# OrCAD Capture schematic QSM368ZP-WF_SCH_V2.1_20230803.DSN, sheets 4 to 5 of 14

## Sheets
4 PAGE04-LVDS&HDMIOUT: size A2
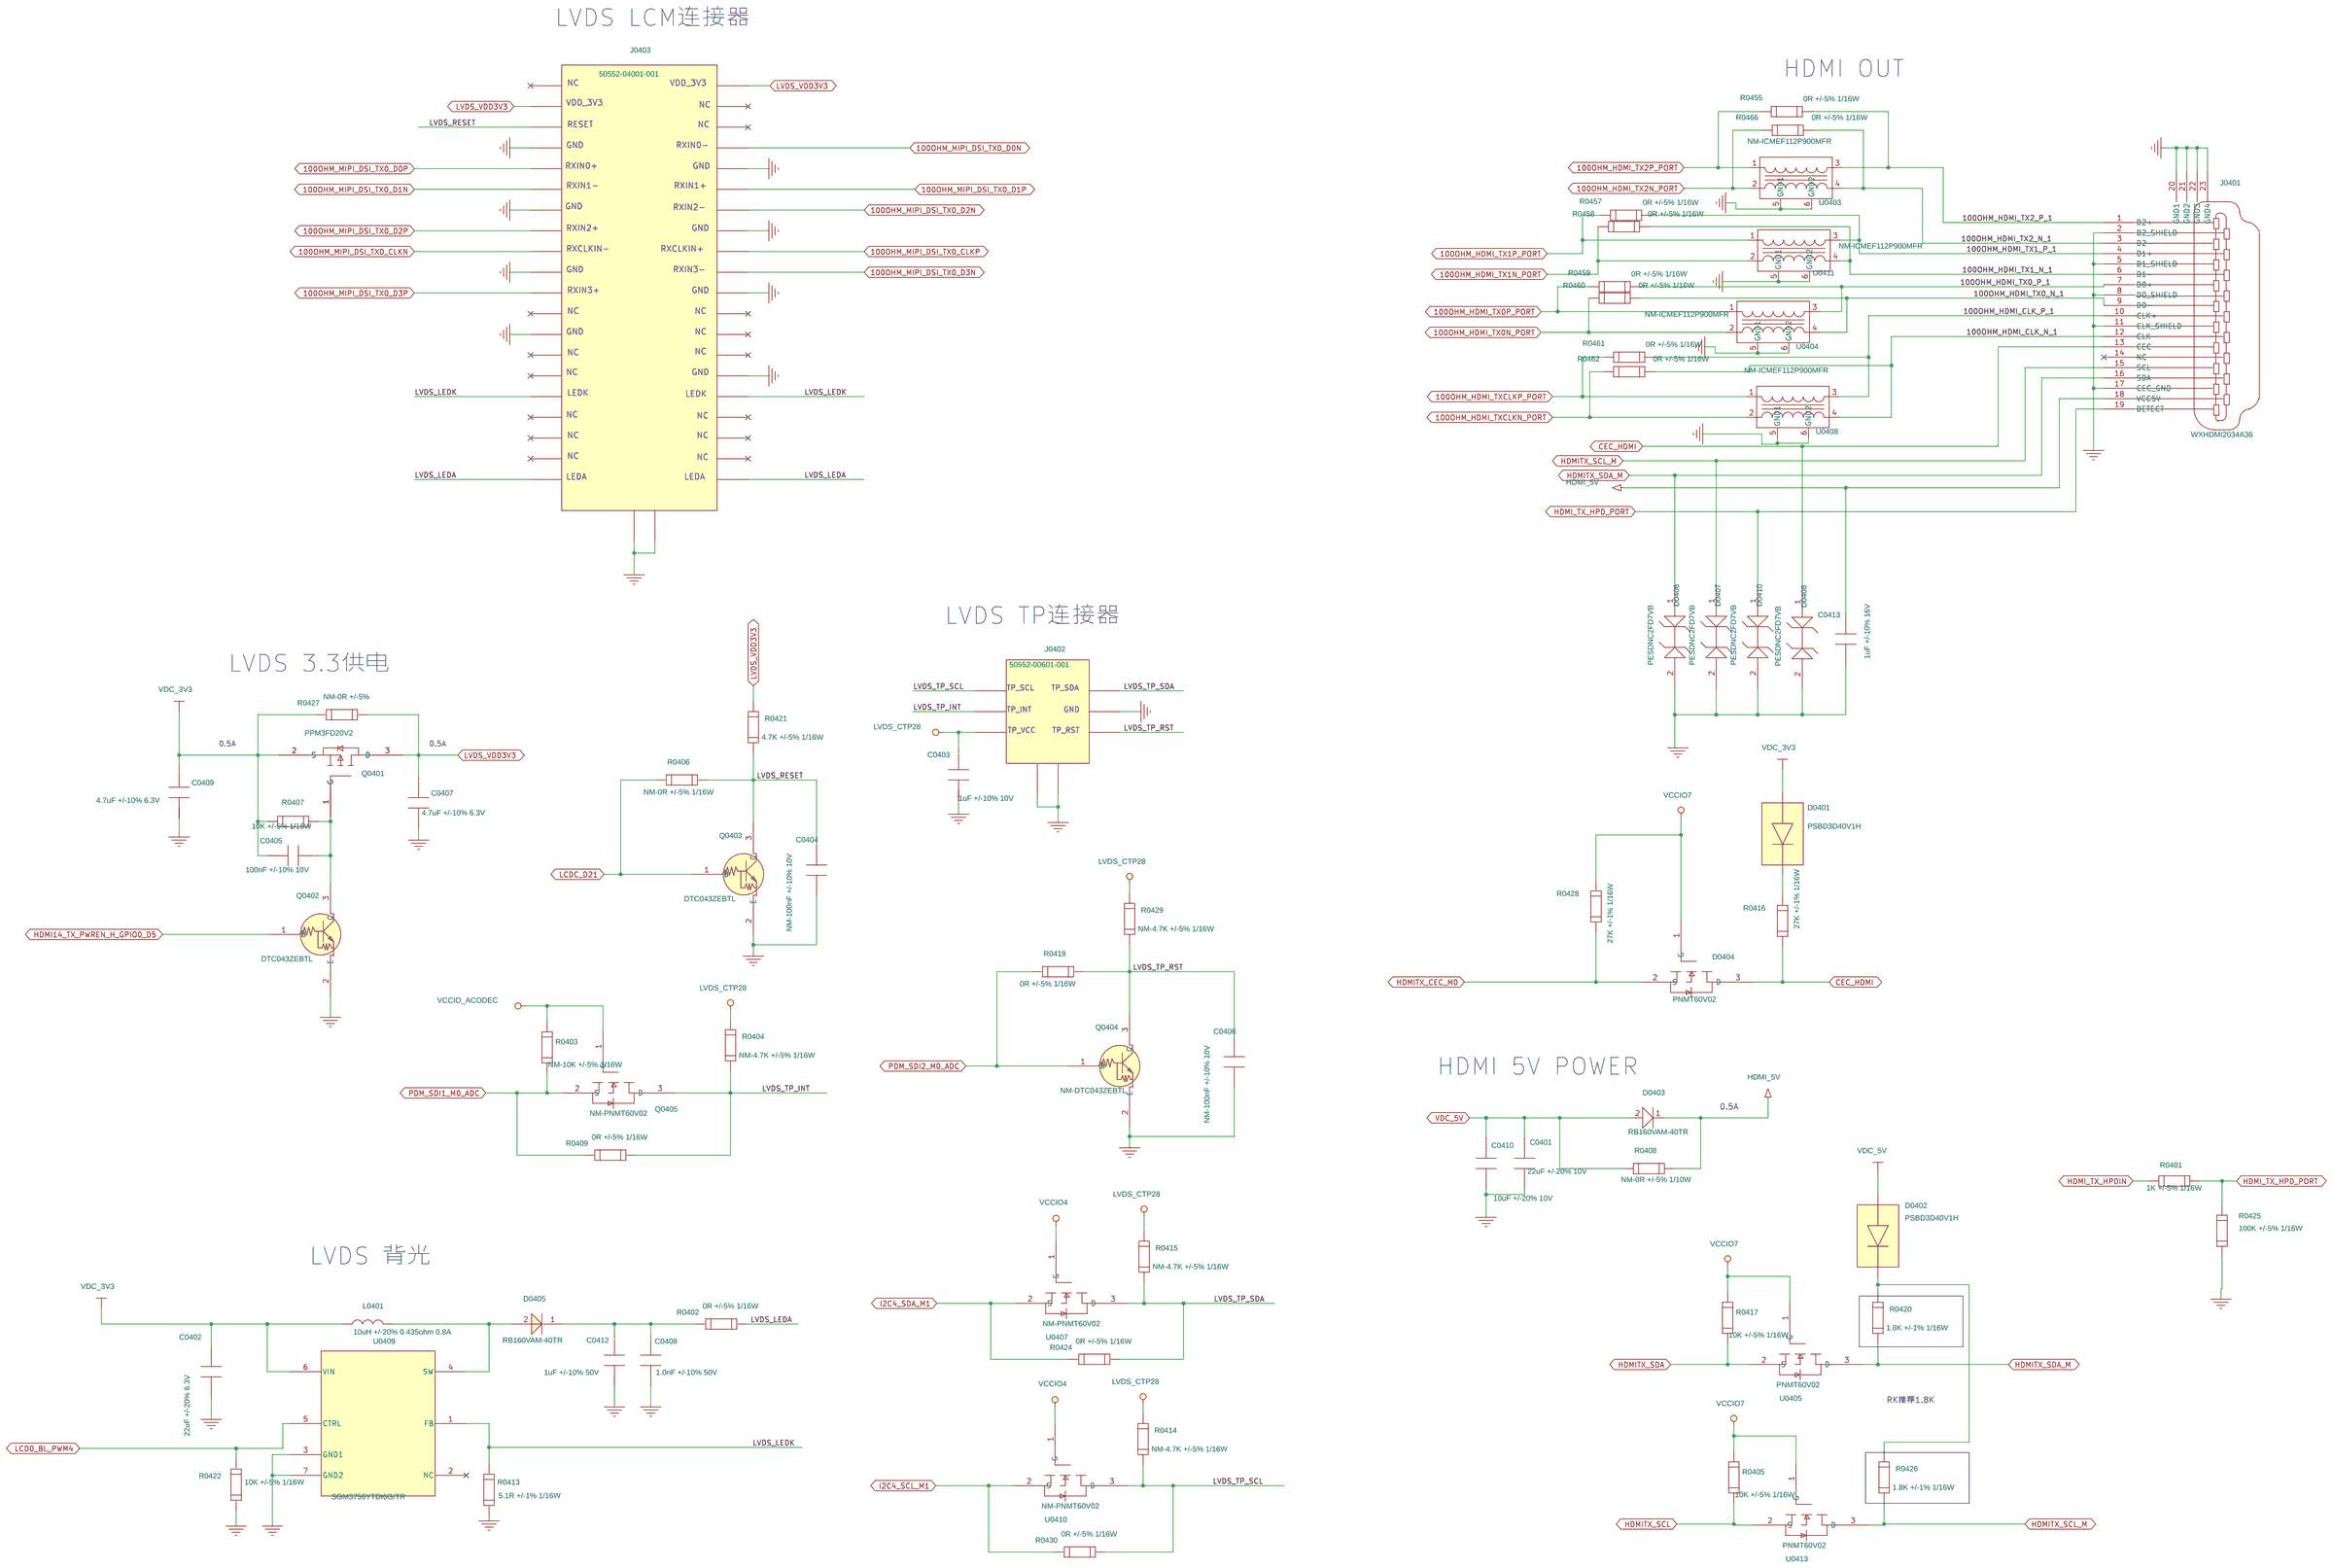
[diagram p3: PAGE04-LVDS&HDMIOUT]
5 PAGE05-MIPI&eDP: size A2
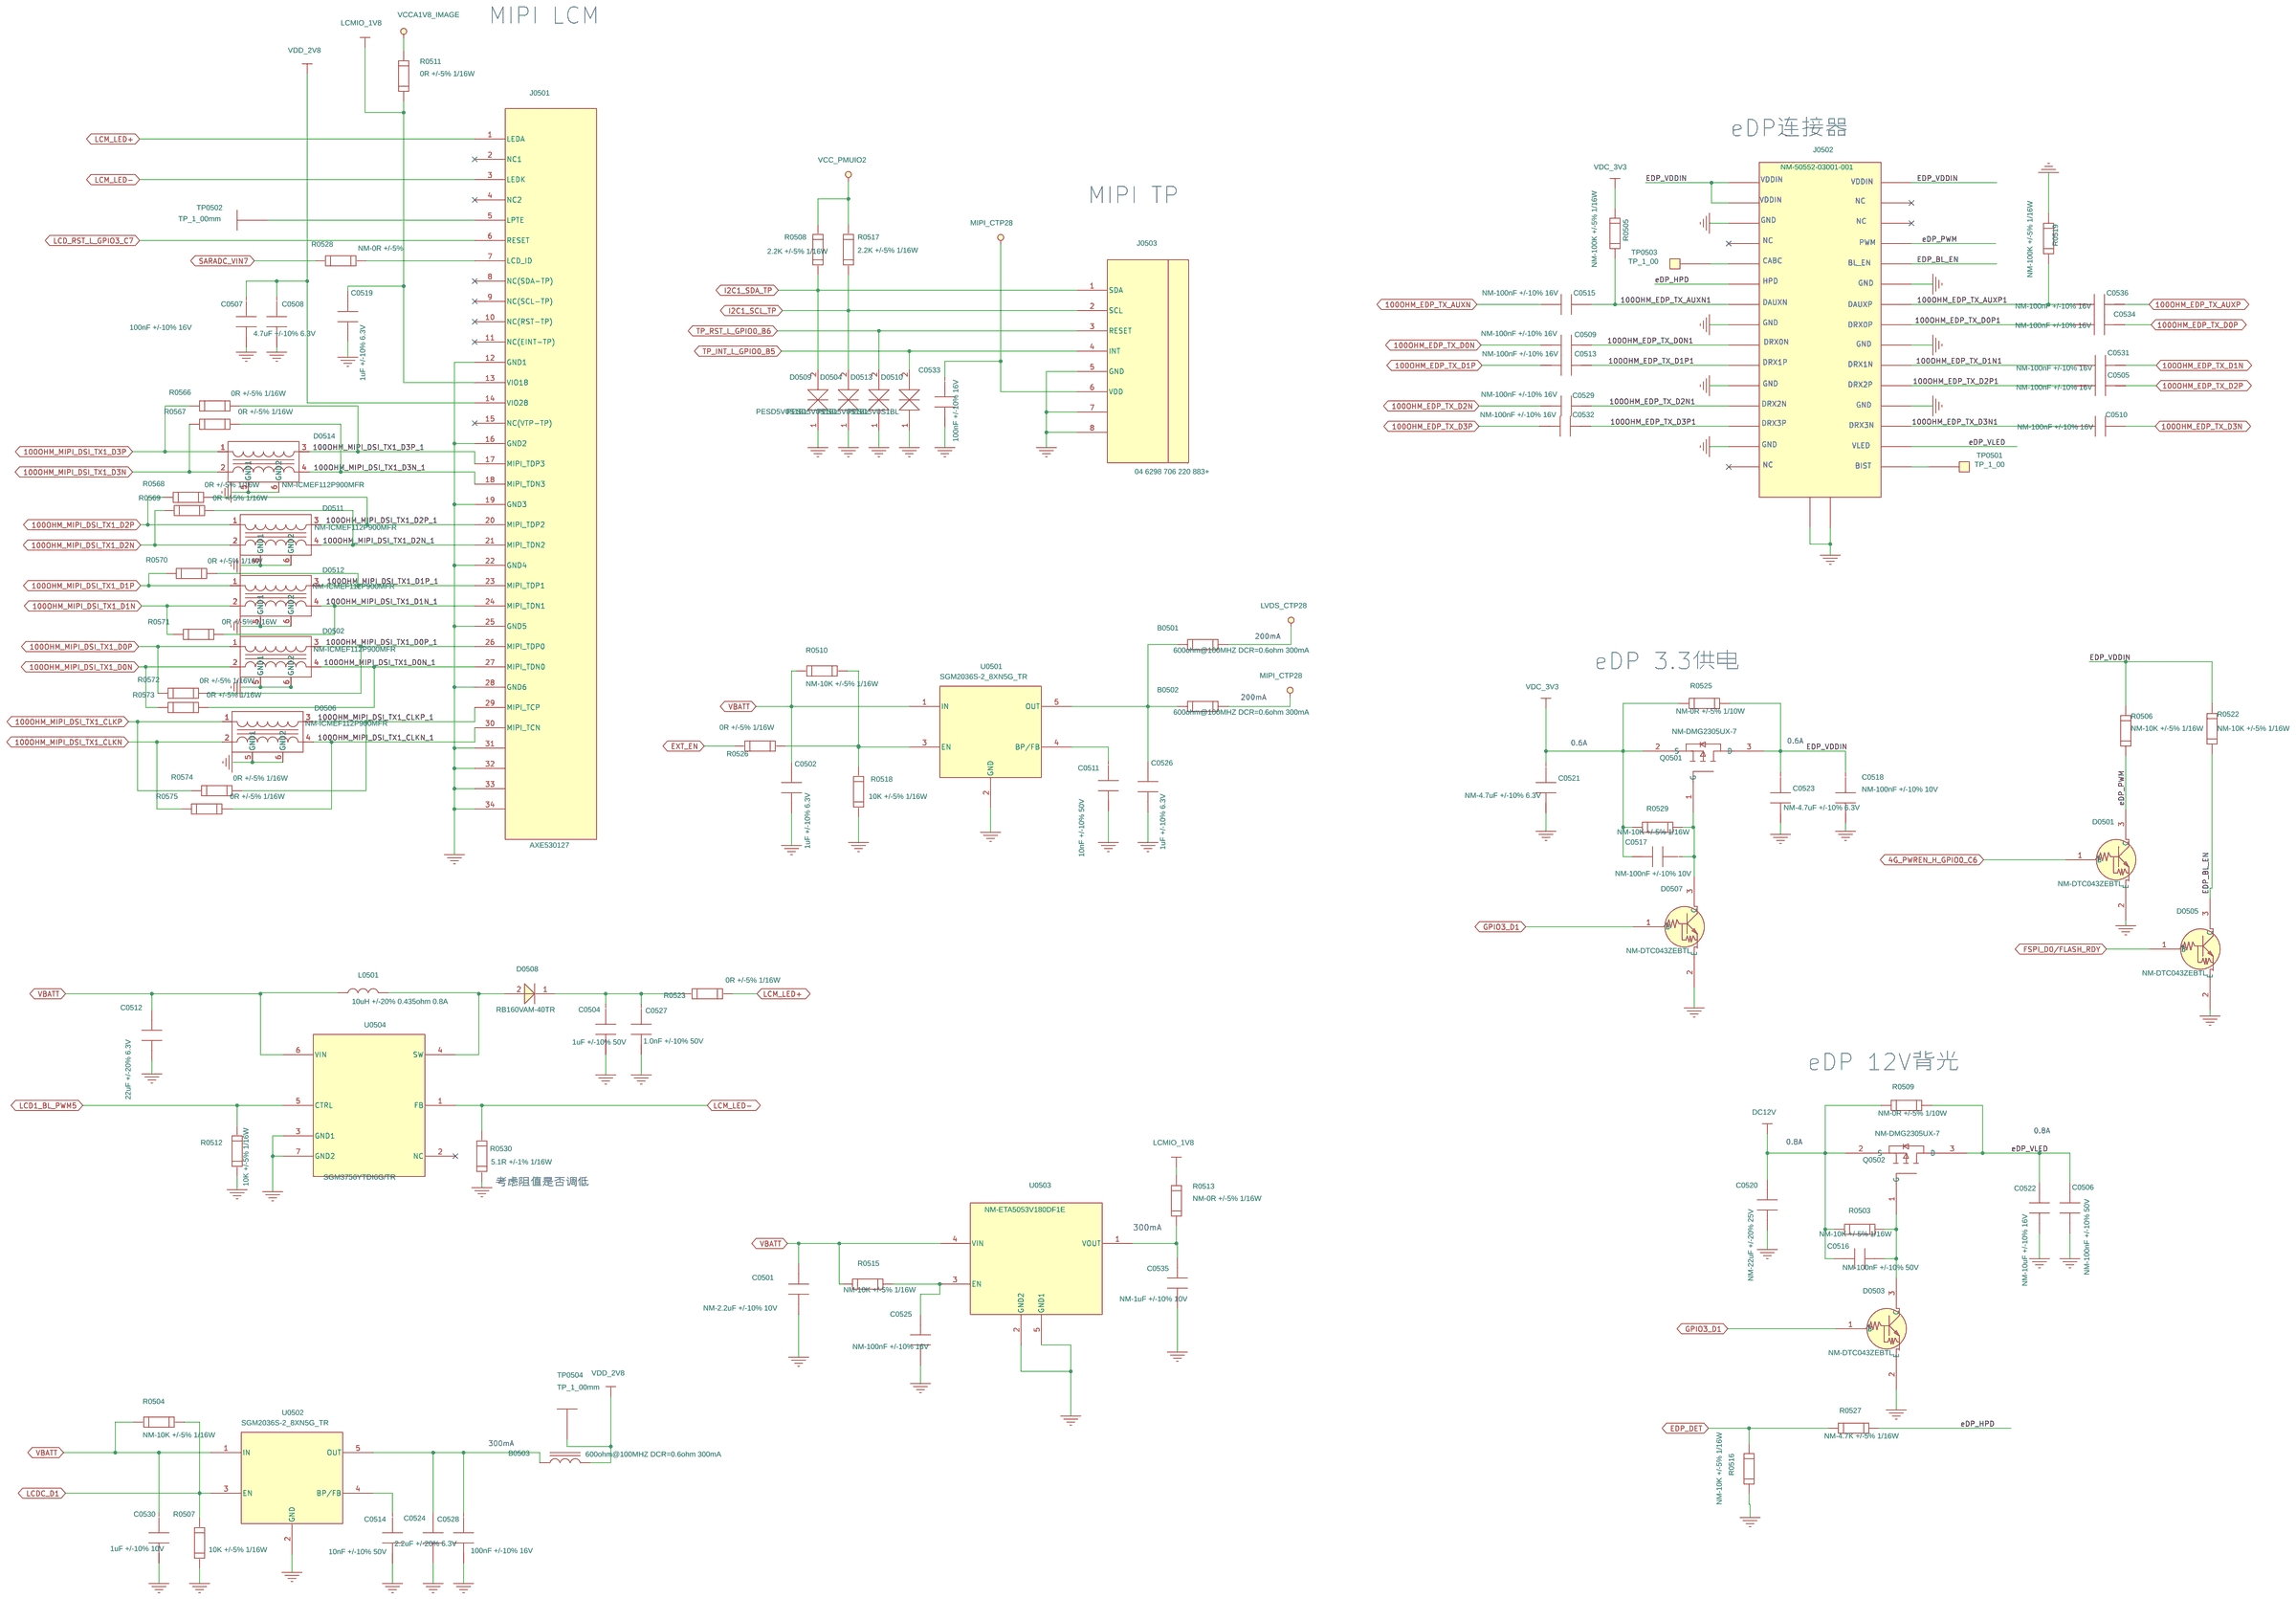
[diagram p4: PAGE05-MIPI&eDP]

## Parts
sheet PAGE04-LVDS&HDMIOUT
C0401  22uF +/-20% 10V  [c-0603_22_47uf_h1_00]
C0402  22uF +/-20% 6.3V  [c-0603_22_47uf_h1_00]
C0403  1uF +/-10% 10V  [C-0402]
C0404  NM-100nF +/-10% 10V  [C-0402]
C0405  100nF +/-10% 10V  [C-0402]
C0406  NM-100nF +/-10% 10V  [C-0402]
C0407  4.7uF +/-10% 6.3V  [C-0603]
C0408  1.0nF +/-10% 50V  [C-0402]
C0409  4.7uF +/-10% 6.3V  [C-0603]
C0410  10uF +/-20% 10V  [c-0603_22_47uf_h1_00]
C0412  1uF +/-10% 50V  [C-0805]
C0413  1uF +/-10% 16V  [C-0603]
D0401  PSBD3D40V1H  [PSBD3D40V1H]
D0402  PSBD3D40V1H  [PSBD3D40V1H]
D0403  RB160VAM-40TR  [RB160VA-40]
D0404  PNMT60V02  [PNMT60V02]
D0405  RB160VAM-40TR  [RB160VA-40]
D0406  PESDNC2FD7VB  [PESDNC2FD7VB]
D0407  PESDNC2FD7VB  [PESDNC2FD7VB]
D0408  PESDNC2FD7VB  [PESDNC2FD7VB]
D0410  PESDNC2FD7VB  [PESDNC2FD7VB]
J0401  WXHDMI2034A36  [WXHDMI2034A36]
J0402  50552-00601-001  [50552-00601-001_PINS8_7D5x3D4]
J0403  50552-04001-001  [50552-04001-001_PINS42_24D5x3D4]
L0401  10uH +/-20% 0.435ohm 0.8A  [L-2520]
Q0401  PPM3FD20V2  [WPM3027]
Q0402  DTC043ZEBTL  [DTC043ZEBTL]
Q0403  DTC043ZEBTL  [DTC043ZEBTL]
Q0404  NM-DTC043ZEBTL  [DTC043ZEBTL]
Q0405  NM-PNMT60V02  [PNMT60V02]
R0401  1K +/-5% 1/16W  [R-0402]
R0402  0R +/-5% 1/16W  [R-0402]
R0403  NM-10K +/-5% 1/16W  [R-0402]
R0404  NM-4.7K +/-5% 1/16W  [R-0402]
R0405  10K +/-5% 1/16W  [R-0402]
R0406  NM-0R +/-5% 1/16W  [R-0402]
R0407  10K +/-5% 1/16W  [R-0402]
R0408  NM-0R +/-5% 1/10W  [R-0603]
R0409  0R +/-5% 1/16W  [R-0402]
R0413  5.1R +/-1% 1/16W  [R-0402]
R0414  NM-4.7K +/-5% 1/16W  [R-0402]
R0415  NM-4.7K +/-5% 1/16W  [R-0402]
R0416  27K +/-1% 1/16W  [R-0402]
R0417  10K +/-5% 1/16W  [R-0402]
R0418  0R +/-5% 1/16W  [R-0402]
R0420  1.8K +/-1% 1/16W  [R-0402]
R0421  4.7K +/-5% 1/16W  [R-0402]
R0422  10K +/-5% 1/16W  [R-0402]
R0424  0R +/-5% 1/16W  [R-0402]
R0425  100K +/-5% 1/16W  [R-0402]
R0426  1.8K +/-1% 1/16W  [R-0402]
R0427  NM-0R +/-5%  [R-0402]
R0428  27K +/-1% 1/16W  [R-0402]
R0429  NM-4.7K +/-5% 1/16W  [R-0402]
R0430  0R +/-5% 1/16W  [R-0402]
R0455  0R +/-5% 1/16W  [R-0402]
R0457  0R +/-5% 1/16W  [R-0402]
R0458  0R +/-5% 1/16W  [R-0402]
R0459  0R +/-5% 1/16W  [R-0402]
R0460  0R +/-5% 1/16W  [R-0402]
R0461  0R +/-5% 1/16W  [R-0402]
R0462  0R +/-5% 1/16W  [R-0402]
R0466  0R +/-5% 1/16W  [R-0402]
U0403  NM-ICMEF112P900MFR  [ICMEF112P900MFR]
U0404  NM-ICMEF112P900MFR  [ICMEF112P900MFR]
U0405  PNMT60V02  [PNMT60V02]
U0407  NM-PNMT60V02  [PNMT60V02]
U0408  NM-ICMEF112P900MFR  [ICMEF112P900MFR]
U0409  SGM3756YTDI6G/TR  [SGM3756YTDI6G_TR_PINS7_2x2]
U0410  NM-PNMT60V02  [PNMT60V02]
U0411  NM-ICMEF112P900MFR  [ICMEF112P900MFR]
U0413  PNMT60V02  [PNMT60V02]
sheet PAGE05-MIPI&eDP
B0501  600ohm@100MHZ DCR=0.6ohm 300mA  [R-0402]
B0502  600ohm@100MHZ DCR=0.6ohm 300mA  [R-0402]
B0503  600ohm@100MHZ DCR=0.6ohm 300mA  [B-0402]
C0501  NM-2.2uF +/-10% 10V  [C-0402]
C0502  1uF +/-10% 6.3V  [C-0402]
C0504  1uF +/-10% 50V  [C-0805]
C0505  NM-100nF +/-10% 16V  [C-0402]
C0506  NM-100nF +/-10% 50V  [C-0603]
C0507  100nF +/-10% 16V  [C-0402]
C0508  4.7uF +/-10% 6.3V  [C-0603]
C0509  NM-100nF +/-10% 16V  [C-0402]
C0510  NM-100nF +/-10% 16V  [C-0402]
C0511  10nF +/-10% 50V  [C-0402]
C0512  22uF +/-20% 6.3V  [c-0603_22_47uf_h1_00]
C0513  NM-100nF +/-10% 16V  [C-0402]
C0514  10nF +/-10% 50V  [C-0402]
C0515  NM-100nF +/-10% 16V  [C-0402]
C0516  NM-100nF +/-10% 50V  [C-0603]
C0517  NM-100nF +/-10% 10V  [C-0402]
C0518  NM-100nF +/-10% 10V  [C-0402]
C0519  1uF +/-10% 6.3V  [C-0402]
C0520  NM-22uF +/-20% 25V  [C-0805_H1_45]
C0521  NM-4.7uF +/-10% 6.3V  [C-0603]
C0522  NM-10uF +/-10% 16V  [C-0805_H1_45]
C0523  NM-4.7uF +/-10% 6.3V  [C-0603]
C0524  2.2uF +/-20% 6.3V  [C-0402]
C0525  NM-100nF +/-10% 16V  [C-0402]
C0526  1uF +/-10% 6.3V  [C-0402]
C0527  1.0nF +/-10% 50V  [C-0402]
C0528  100nF +/-10% 16V  [C-0402]
C0529  NM-100nF +/-10% 16V  [C-0402]
C0530  1uF +/-10% 10V  [C-0402]
C0531  NM-100nF +/-10% 16V  [C-0402]
C0532  NM-100nF +/-10% 16V  [C-0402]
C0533  100nF +/-10% 16V  [C-0402]
C0534  NM-100nF +/-10% 16V  [C-0402]
C0535  NM-1uF +/-10% 10V  [C-0402]
C0536  NM-100nF +/-10% 16V  [C-0402]
D0501  NM-DTC043ZEBTL  [DTC043ZEBTL]
D0502  NM-ICMEF112P900MFR  [ICMEF112P900MFR]
D0503  NM-DTC043ZEBTL  [DTC043ZEBTL]
D0504  PESD5V0S1BL  [PESD5V0S1BL]
D0505  NM-DTC043ZEBTL  [DTC043ZEBTL]
D0506  NM-ICMEF112P900MFR  [ICMEF112P900MFR]
D0507  NM-DTC043ZEBTL  [DTC043ZEBTL]
D0508  RB160VAM-40TR  [RB160VA-40]
D0509  PESD5V0S1BL  [PESD5V0S1BL]
D0510  PESD5V0S1BL  [PESD5V0S1BL]
D0511  NM-ICMEF112P900MFR  [ICMEF112P900MFR]
D0512  NM-ICMEF112P900MFR  [ICMEF112P900MFR]
D0513  PESD5V0S1BL  [PESD5V0S1BL]
D0514  NM-ICMEF112P900MFR  [ICMEF112P900MFR]
J0501  AXE530127  [AXE530127]
J0502  NM-50552-03001-001  [50552-03001-001_PINS32_19D5x3D4]
J0503  04 6298 706 220 883+  [6298706220883]
L0501  10uH +/-20% 0.435ohm 0.8A  [L-2520]
Q0501  NM-DMG2305UX-7  [DMG2305UX-7]
Q0502  NM-DMG2305UX-7  [DMG2305UX-7]
R0503  NM-10K +/-5% 1/16W  [R-0402]
R0504  NM-10K +/-5% 1/16W  [R-0402]
R0505  NM-100K +/-5% 1/16W  [R-0402]
R0506  NM-10K +/-5% 1/16W  [R-0402]
R0507  10K +/-5% 1/16W  [R-0402]
R0508  2.2K +/-5% 1/16W  [R-0402]
R0509  NM-0R +/-5% 1/10W  [R-0603]
R0510  NM-10K +/-5% 1/16W  [R-0402]
R0511  0R +/-5% 1/16W  [R-0402]
R0512  10K +/-5% 1/16W  [R-0402]
R0513  NM-0R +/-5% 1/16W  [R-0402]
R0515  NM-10K +/-5% 1/16W  [R-0402]
R0516  NM-10K +/-5% 1/16W  [R-0402]
R0517  2.2K +/-5% 1/16W  [R-0402]
R0518  10K +/-5% 1/16W  [R-0402]
R0519  NM-100K +/-5% 1/16W  [R-0402]
R0522  NM-10K +/-5% 1/16W  [R-0402]
R0523  0R +/-5% 1/16W  [R-0402]
R0525  NM-0R +/-5% 1/10W  [R-0603]
R0526  0R +/-5% 1/16W  [R-0402]
R0527  NM-4.7K +/-5% 1/16W  [R-0402]
R0528  NM-0R +/-5%  [R-0402]
R0529  NM-10K +/-5% 1/16W  [R-0402]
R0530  5.1R +/-1% 1/16W  [R-0402]
R0566  0R +/-5% 1/16W  [R-0402]
R0567  0R +/-5% 1/16W  [R-0402]
R0568  0R +/-5% 1/16W  [R-0402]
R0569  0R +/-5% 1/16W  [R-0402]
R0570  0R +/-5% 1/16W  [R-0402]
R0571  0R +/-5% 1/16W  [R-0402]
R0572  0R +/-5% 1/16W  [R-0402]
R0573  0R +/-5% 1/16W  [R-0402]
R0574  0R +/-5% 1/16W  [R-0402]
R0575  0R +/-5% 1/16W  [R-0402]
TP0501  TP_1_00  [TP_1_00]
TP0502  TP_1_00mm  [TP_1_00]
TP0503  TP_1_00  [TP_1_00]
TP0504  TP_1_00mm  [TP_1_00]
U0501  SGM2036S-2_8XN5G_TR  [SGM2036S-2_8XN5G_TR_PINS5_2D92X1D6]
U0502  SGM2036S-2_8XN5G_TR  [SGM2036S-2_8XN5G_TR_PINS5_2D92X1D6]
U0503  NM-ETA5053V180DF1E  [ETA5053V180DF1E]
U0504  SGM3756YTDI6G/TR  [SGM3756YTDI6G_TR_PINS7_2x2]

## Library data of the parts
C0401 = c-0603_22_47uf_H1_00: Application_Level: 通用; DataRecord: 2017-08-09; Geometry Height: 1.0mm; Lib_Name: 电容; MPN: CC0603MRX5R6BB226; Manufacturer: YAGEO; Part Description: CAP X5R 22uF +/-20% 10V CH0603 1.6x0.8mm H1mm RO; Part Number: QT0012102005; Rev.Date: 2022-09-21
C0402 C0512 = c-0603_22_47uf_H1_00: Application_Level: 通用; DataRecord: 2017-08-09; Geometry Height: 1MM; Lib_Name: 电容; MPN: CC0603MRX5R5BB226; Manufacturer: YAGEO; Part Description: CAP X5R 22uF +/-20% 6.3V CH0603 1.6x0.8mm H1mm RO; Part Number: QT0012000626; Rev.Date: 2022-09-21
C0403 C0530 = C-0402_v2: DataRecord: 2017-08-09; Geometry Height: 0.5mm; MPN: CC0402KRX5R6BB105; Manufacturer: YAGEO; Part Description: CAP X5R 1uF +/-10% 10V CH0402 H0.55mm RO; Part Number: QT0012000349; Rev.Date: 2022-08-17; SCH Part: C
C0404 C0406 = C: Application_Level: Common(通用); BOMRemark: NM; DataRecord: 2017-08-09; Geometry Height: 0.5mm; Lib_Name: 电容; MPN: CC0402KRX7R6BB104; Manufacturer: YAGEO; Part Description: CAP X7R 100nF +/-10% 10V CH0402 H0.55mm RO; Part Number: QT0012000328; Rev.Date: 2021-12-15
C0405 = C-0402_v2: DataRecord: 2017-08-09; Geometry Height: 0.5mm; MPN: CC0402KRX7R6BB104; Manufacturer: YAGEO; Part Description: CAP X7R 100nF +/-10% 10V CH0402 H0.55mm RO; Part Number: QT0012000328; Rev.Date: 2022-08-17; SCH Part: C
C0407 C0409 C0508 = C-0603: DataRecord: 2017-08-09; Geometry Height: 0.8mm; Geometry.Height: 0.5mm; MPN: CC0603KRX5R5BB475; Manufacturer: YAGEO; Part Description: CAP X5R 4.7uF +/-10% 6.3V CH0603 H0.9mm RO; Part Number: QT0012100596; Rev.Date: 2022-08-17; SCH Part: C
C0408 C0527 = C-0402_v2: DataRecord: 2017-08-09; Geometry Height: 0.5mm; MPN: CC0402KRX7R9BB102; Manufacturer: YAGEO; Part Description: CAP X7R 1.0nF +/-10% 50V CH0402 H0.55mm RO; Part Number: QT0012100276; Rev.Date: 2022-08-17; SCH Part: C
C0410 = c-0603_22_47uf_H1_00: Application_Level: 通用; DataRecord: 2017-08-09; Geometry Height: 1MM; Lib_Name: 电容; MPN: CC0603MRX5R6BB106; Manufacturer: YAGEO; Part Description: CAP X5R 10uF +/-20% 10V CH0603 1.6x0.8mm H1mm RO; Part Number: QT0012001350; Rev.Date: 2022-09-21
C0412 C0504 = C-0805_v2: DataRecord: 2017-08-09; Geometry Height: 1.45MM; MPN: CC0805KKX7R9BB105; Manufacturer: YAGEO; Part Description: CAP X7R 1uF +/-10% 50V CH0805 H1.45mm RO; Part Number: QT0012002024; Rev.Date: 2022-08-17; SCH Part: C-0805_H1_45
C0413 = C: Application_Level: Limited(限制); DataRecord: 2017-08-09; Geometry Height: 0.8mm; Lib_Name: 电容; MPN: CC0603KRX5R7BB105; Manufacturer: YAGEO; Part Description: CAP X5R 1uF +/-10% 16V CH0603 H0.9mm RO; Part Number: QT0012000033; Rev.Date: 2022-08-17
D0401 D0402 = PSBD3D40V1H: Application_Level: Common(通用); DataRecord: 2020-02-20; Geometry Height: 1.0mm; Lib_Name: 二极管; Manufacturer: PRISEMI; Part Description: DIO Schottky Vr=40V IF=1A SOD-323 RO; Part Number: QT0015101060; Rev.Date: 2022-09-20
D0403 = RB160VA-40_v2: Application_Level: Common(通用); DataRecord: 2018-06-26; Geometry Height: 0.5mm; Lib_Name: 二极管; Manufacturer: ROHM; Part Description: DIO Schottky Vr=40V IF=1A TUMD2M RO; Part Number: QT0015101042; Rev.Date: 2022-08-17
D0404 U0405 U0413 = PNMT60V02: Application_Level: Common(通用); DataRecord: 2020-05-25; Geometry Height: 1.11mm; Lib_Name: MOS管; Manufacturer: PRISEMI; Part Description: AUD NMOS VDS=60V 0.18A Vth=0.5~1.5V SOT-23 RO; Part Number: QT0015401037; Rev.Date: 2022-09-20
D0405 D0508 = RB160VA-40: DataRecord: 2018-06-26; Geometry Height: 0.5mm; Manufacturer: ROHM; Part Description: DIO Schottky Vr=40V IF=1A TUMD2M RO; Part Number: QT0015101042; Rev.Date: 2022-08-17
D0406 D0407 D0408 D0410 = PESDNC2FD7VB: Application_Level: Common(通用); DataRecord: 2020-03-06; Geometry Height: 0.5mm; Lib_Name: ESD&EMI&TVS; Manufacturer: PRISEMI; Part Description: TVS Bi Vrwm=7V 21pF DFN1006-2L RO; Part Number: QT0013501082; Rev.Date: 2022-09-20
J0401 = WXHDMI2034A36: Application_Level: 限制（Others）; DataRecord: 2017-08-09; Geometry Height: 6.1mm; Lib_Name: 结构连接器; Manufacturer: XINGWANG; Part Description: CON TYPE-A HDMI FEMALE 19PIN 0.5PITCH 15x14mm H6.1mm RO; Part Number: QT0016601009; Rev.Date: 2022-08-17
J0402 = 50552-00601-001: Application_Level: 限制（Others）; DataRecord: 2023-02-22; Geometry Height: 4.35mm; Lib_Name: 结构连接器; Manufacturer: ACES; Part Description: CON BTB FEMALE 2x3Pin 1.0pitch SMT PINS8 7.5x3.4mm H4.35mm RO; Part Number: QT0016201827; Rev.Date: 2023-02-22
J0403 = 50552-04001-001: Application_Level: 限制（Others）; DataRecord: 2023-02-22; Geometry Height: 4.35mm; Lib_Name: 结构连接器; Manufacturer: ACES; Part Description: CON BTB FEMALE 2x20Pin 1.0pitch SMT PINS42 24.5x3.4mm H4.35mm RO; Part Number: QT0016201829; Rev.Date: 2023-02-22
L0401 L0501 = L: Application_Level: 通用; DataRecord: 2017-09-05; Geometry Height: 1.0mm; Lib_Name: 电感&磁珠; MPN: WPN252010HS100MT; Manufacturer: SUNLORD; Part Description: IND LOW 10uH +/-20% 0.435ohm 0.8A 2.5x2.0mm H1.0mm RO; Part Number: QT0014103254; Rev.Date: 2022-08-17
Q0401 = WPM3027: Application_Level: Common(通用); DataRecord: 2022-10-14; Geometry Height: 0.498mm; Lib_Name: MOS管; Manufacturer: PRISEMI; Part Description: AUD PMOS VDS=-20V -2A Vth=-0.45~-0.85V R19 DFN1006-3L PINS3 0.98x0.58mm H0.498mm RO; Part Number: QT0015401117; Rev.Date: 2022-10-14
Q0402 Q0403 = DTC043ZEBTL: Application_Level: Common(通用); DataRecord: 2017-08-09; Geometry Height: 0.6mm; Lib_Name: 三极管; Manufacturer: ROHM; Part Description: AUD Digital NPN 50V 100mA R1=4.7K R2=47K EMT3F RO; Part Number: QT0015200080; Rev.Date: 2022-08-17
D0501 D0503 D0505 D0507 Q0404 = DTC043ZEBTL: Application_Level: Common(通用); BOMRemark: NM; DataRecord: 2017-08-09; Geometry Height: 0.6mm; Lib_Name: 三极管; Manufacturer: ROHM; Part Description: AUD Digital NPN 50V 100mA R1=4.7K R2=47K EMT3F RO; Part Number: QT0015200080; Rev.Date: 2021-12-15
Q0405 U0407 U0410 = PNMT60V02: Application_Level: Common(通用); BOMRemark: NM; DataRecord: 2020-05-25; Geometry Height: 1.11mm; Lib_Name: MOS管; Manufacturer: PRISEMI; Part Description: AUD NMOS VDS=60V 0.18A Vth=0.5~1.5V SOT-23 RO; Part Number: QT0015401037; Rev.Date: 2021-10-25
R0401 = R-0402: Application_Level: 通用; DataRecord: 2017-08-09; Geometry Height: 0.4MM; Lib_Name: 电阻; MPN: RC0402JR-071KL; Manufacturer: YAGEO; Part Description: RES MF 1K +/-5% 1/16W CH0402 H0.4mm RO; Part Number: QT0011000489; Rev.Date: 2022-08-17
R0402 R0409 R0424 R0430 R0523 R0526 = R-0402_v3: DataRecord: 2017-08-09; Geometry Height: 0.4MM; MPN: RC0402JR-070RL; Manufacturer: YAGEO; Part Description: RES MF 0R +/-5% 1/16W CH0402 H0.4mm RO; Part Number: QT0011000094; Rev.Date: 2022-08-17
R0403 = R-0402: Application_Level: 通用; BOMRemark: NM; DataRecord: 2017-08-09; Geometry Height: 0.4MM; Lib_Name: 电阻; MPN: RC0402JR-0710KL; Manufacturer: YAGEO; Part Description: RES MF 10K +/-5% 1/16W CH0402 H0.4mm RO; Part Number: QT0011000453; Rev.Date: 2022-08-17
R0404 R0414 R0415 R0429 = R-0402: Application_Level: Common(通用); BOMRemark: NM; DataRecord: 2017-08-09; Geometry Height: 0.4MM; Lib_Name: 电阻; MPN: RC0402JR-074K7L; Manufacturer: YAGEO; Part Description: RES MF 4.7K +/-5% 1/16W CH0402 H0.4mm RO; Part Number: QT0011000456; Rev.Date: 2021-12-15
R0405 R0417 = R-0402: Application_Level: 通用; DataRecord: 2017-08-09; Geometry Height: 0.4MM; Lib_Name: 电阻; MPN: RC0402JR-0710KL; Manufacturer: YAGEO; Part Description: RES MF 10K +/-5% 1/16W CH0402 H0.4mm RO; Part Number: QT0011000453; Rev.Date: 2022-08-17
R0406 = R-0402_v3: Application_Level: Common(通用); BOMRemark: NM; DataRecord: 2017-08-09; Geometry Height: 0.4MM; Lib_Name: 电阻; MPN: RC0402JR-070RL; Manufacturer: YAGEO; Part Description: RES MF 0R +/-5% 1/16W CH0402 H0.4mm RO; Part Number: QT0011000094; Rev.Date: 2021-12-15
R0407 = R-0402: Application_Level: Common(通用); DataRecord: 2017-08-09; Geometry Height: 0.4MM; Lib_Name: 电阻; MPN: RC0402JR-0710KL; Manufacturer: YAGEO; Part Description: RES MF 10K +/-5% 1/16W CH0402 H0.4mm RO; Part Number: QT0011000453; Rev.Date: 2022-08-17
R0408 R0509 R0525 = R-0603: Application_Level: 通用; BOMRemark: NM; DataRecord: 2017-08-09; Geometry Height: 0.55MM; Lib_Name: 电阻; MPN: RC0603JR-070RL; Manufacturer: YAGEO; Part Description: RES MF 0R +/-5% 1/10W CH0603 H0.55mm RO; Part Number: QT0011000610; Rev.Date: 2022-08-17
R0413 R0530 = R-0402_v3: Application_Level: 通用; DataRecord: 2017-08-09; Geometry Height: 0.4MM; Lib_Name: 电阻; MPN: RC0402FR-075R1L; Manufacturer: YAGEO; Part Description: RES MF 5.1R +/-1% 1/16W CH0402 H0.4mm RO; Part Number: QT0011003032; Rev.Date: 2022-08-17
R0416 R0428 = R-0402: Application_Level: 通用; DataRecord: 2017-08-09; Geometry Height: 0.4MM; Lib_Name: 电阻; MPN: RC0402FR-0727KL; Manufacturer: YAGEO; Part Description: RES MF 27K +/-1% 1/16W CH0402 H0.4mm RO; Part Number: QT0011003062; Rev.Date: 2022-08-17
R0418 = R-0402_v3: Application_Level: Common(通用); DataRecord: 2017-08-09; Geometry Height: 0.4MM; Lib_Name: 电阻; MPN: RC0402JR-070RL; Manufacturer: YAGEO; Part Description: RES MF 0R +/-5% 1/16W CH0402 H0.4mm RO; Part Number: QT0011000094; Rev.Date: 2022-08-17
R0420 R0426 = R-0402: Application_Level: Common(通用); DataRecord: 2022-10-27; Geometry Height: 0.4mm; Lib_Name: 电阻; MPN: RC0402FR-071K8L; Manufacturer: YAGEO; Part Description: RES MF 1.8K +/-1% 1/16W CH0402 H0.4mm RO; Part Number: QT0011005299; Rev.Date: 2022-10-27
R0421 = R-0402: Application_Level: Common(通用); DataRecord: 2017-08-09; Geometry Height: 0.4MM; Lib_Name: 电阻; MPN: RC0402JR-074K7L; Manufacturer: YAGEO; Part Description: RES MF 4.7K +/-5% 1/16W CH0402 H0.4mm RO; Part Number: QT0011000456; Rev.Date: 2022-08-17
R0422 R0507 R0512 R0518 = R-0402_v3: DataRecord: 2017-08-09; Geometry Height: 0.4MM; MPN: RC0402JR-0710KL; Manufacturer: YAGEO; Part Description: RES MF 10K +/-5% 1/16W CH0402 H0.4mm RO; Part Number: QT0011000453; Rev.Date: 2022-08-17
R0425 = R-0402: Application_Level: 通用; DataRecord: 2017-08-09; Geometry Height: 0.4MM; Lib_Name: 电阻; MPN: RC0402JR-07100KL; Manufacturer: YAGEO; Part Description: RES MF 100K +/-5% 1/16W CH0402 H0.4mm RO; Part Number: QT0011000450; Rev.Date: 2022-08-17
R0427 = R-0402_v3: BOMRemark: NM; MPN: RC0402JR-070RL; Manufacturer: YAGEO; Part Description: RES MF 0R +/-5% 1/16W CH0402 H0.4mm RO; Part Number: QT0011000094
R0455 R0457 R0458 R0459 R0460 R0461 R0462 R0466 R0511 R0566 R0567 R0568 R0569 R0570 R0571 R0572 R0573 R0574 R0575 = R-0402: Application_Level: Common(通用); DataRecord: 2017-08-09; Geometry Height: 0.4MM; Lib_Name: 电阻; MPN: RC0402JR-070RL; Manufacturer: YAGEO; Part Description: RES MF 0R +/-5% 1/16W CH0402 H0.4mm RO; Part Number: QT0011000094; Rev.Date: 2022-08-17
U0403 U0404 U0408 U0411 = ICMEF112P900MFR: Application_Level: 通用; BOMRemark: NM; DataRecord: 2017-08-09; Geometry Height: 0.65mm; Lib_Name: ESD&EMI&TVS; Manufacturer: ICT; Part Description: ESD+EMI 2CH Wrwm=10V 0.8-1.7pF 0.1-3.0R 6Pin 1.0x1.27mm H0.65mm RO; Part Number: QT0013501003; Rev.Date: 2022-08-17
U0409 U0504 = SGM3756YTDI6G_TR: Application_Level: Common(通用); DataRecord: 2022-08-26; Geometry Height: 0.8; Lib_Name: 驱动芯片; Manufacturer: SGMICRO; Part Description: IC LED Driver Backlight 1.5A TDFN-2x2-6L PINS7 2x2mm H0.8mm RO; Part Number: QT0013901490; Rev.Date: 2023-03-10
B0501 B0502 = R-0402_NM: DataRecord: 2017-08-09; Geometry Height: 0.55mm; MPN: BK1005HW601-T; Manufacturer: TAIYO; Part Description: BEAD 600ohm@100MHZ DCR=0.6ohm 300mA CH0402 H0.5mm RO; Part Number: QT0014101548; Rev.Date: 2022-08-17; SCH Part: B
B0503 = B: Application_Level: Common(通用); DataRecord: 2017-08-09; Geometry Height: 0.55mm; Lib_Name: 电感&磁珠; MPN: BK1005HW601-T; Manufacturer: TAIYO; Part Description: BEAD 600ohm@100MHZ DCR=0.6ohm 300mA CH0402 H0.5mm RO; Part Number: QT0014101548; Rev.Date: 2022-08-17
C0501 = C-0402: Application_Level: 限制（Others）; BOMRemark: NM; DataRecord: 2021-09-10; Geometry Height: 0.57mm; Lib_Name: 电容; MPN: CL05A225KP5NSNC; Manufacturer: SAMSUNG; Part Description: CAP X5R 2.2uF +/-10% 10V CH0402 H0.57mm RO; Part Number: QT0012003613; Rev.Date: 2022-08-17
C0502 C0519 C0526 = C: Application_Level: 通用; DataRecord: 2017-08-09; Geometry Height: 0.5mm; Lib_Name: 电容; MPN: CC0402KRX5R5BB105; Manufacturer: YAGEO; Part Description: CAP X5R 1uF +/-10% 6.3V CH0402 H0.55mm RO; Part Number: QT0012100534; Rev.Date: 2022-08-17
C0505 C0509 C0510 C0513 C0525 C0529 C0531 C0532 C0534 = C: Application_Level: Common(通用); BOMRemark: NM; DataRecord: 2017-08-09; Geometry Height: 0.5mm; Lib_Name: 电容; MPN: CC0402KRX7R6BB104; Manufacturer: YAGEO; Part Description: CAP X7R 100nF +/-10% 16V CH0402 H0.55mm RO; Part Number: QT0012100748; Rev.Date: 2021-12-15
C0506 C0516 = C: Application_Level: Non-common(非通用); BOMRemark: NM; DataRecord: 2017-08-09; Geometry Height: 0.8mm; Lib_Name: 电容; MPN: CC0603KRX7R9BB104; Manufacturer: YAGEO; Part Description: CAP X7R 100nF +/-10% 50V CH0603 H0.9mm RO; Part Number: QT0012000587; Rev.Date: 2021-12-15
C0507 C0528 C0533 = C-0402_v2: DataRecord: 2017-08-09; Geometry Height: 0.5mm; MPN: CC0402KRX7R7BB104; Manufacturer: YAGEO; Part Description: CAP X7R 100nF +/-10% 16V CH0402 H0.55mm RO; Part Number: QT0012100748; Rev.Date: 2022-08-17; SCH Part: C
C0511 C0514 = C-0402_v2: DataRecord: 2017-08-09; Geometry Height: 0.5mm; MPN: CC0402KRX7R9BB103; Manufacturer: YAGEO; Part Description: CAP X7R 10nF +/-10% 50V CH0402 H0.55mm RO; Part Number: QT0012100675; Rev.Date: 2022-08-17; SCH Part: C
C0515 C0536 = C: Application_Level: 通用; BOMRemark: NM; DataRecord: 2017-08-09; Geometry Height: 0.5mm; Lib_Name: 电容; MPN: CC0402KRX7R7BB104; Manufacturer: YAGEO; Part Description: CAP X7R 100nF +/-10% 16V CH0402 H0.55mm RO; Part Number: QT0012100748; Rev.Date: 2022-08-17
C0517 C0518 = C-0402_v2: BOMRemark: NM; Manufacturer: YAGEO; Part Description: CAP X7R 100nF +/-10% 10V CH0402 RO; Part Number: QT0012000328
C0520 = C-0805_H1_45: Application_Level: Limited(限制); BOMRemark: NM; DataRecord: 2020-01-09; Geometry Height: 1.45mm; Lib_Name: 电容; MPN: GRM21BR61E226ME44L; Manufacturer: MURATA; Part Description: CAP X5R 22uF +/-20% 25V CH0805 H1.45mm RO; Part Number: QT0012002582; Rev.Date: 2021-10-25
C0521 C0523 = C-0603: BOMRemark: NM; Geometry.Height: 0.5mm; Manufacturer: YAGEO; Part Description: CAP X5R 4.7uF +/-10% 6.3V CH0603 RO; Part Number: QT0012100596
C0522 = C-0805_H1_45: Application_Level: Common(通用); BOMRemark: NM; DataRecord: 2017-08-09; Geometry Height: 1.45mm; Lib_Name: 电容; MPN: CC0805KKX5R7BB106; Manufacturer: YAGEO; Part Description: CAP X5R 10uF +/-10% 16V CH0805 H1.45mm RO; Part Number: QT0012001358; Rev.Date: 2021-12-15
C0524 = C: Application_Level: 通用; DataRecord: 2017-08-09; Geometry Height: 0.5mm; Lib_Name: 电容; MPN: CC0402MRX5R5BB225; Manufacturer: YAGEO; Part Description: CAP X5R 2.2uF +/-20% 6.3V CH0402 H0.55mm RO; Part Number: QT0012000575; Rev.Date: 2022-08-17
C0535 = C-0402_X5R_10UF: BOMRemark: NM; DataRecord: 2017-08-09; Geometry Height: 0.5mm; MPN: CC0402KRX5R6BB105; Part Description: CAP X5R 1uF +/-10% 10V CH0402 H0.55mm RO; Part Number: QT0012000349; Rev.Date: 2021-10-11; SCH Part: C
D0502 D0506 D0511 D0512 D0514 = ICMEF112P900MFR: BOMRemark: NM; Geometry.Height: 0.65mm; Manufacturer: ICT; Part Description: ESD+EMI 2CH Wrwm=10V 0.8-1.7pF 0.1-3.0R 6Pin 1.0x1.27mm H0.65mm RO; Part Number: QT0013501003
D0504 D0509 D0510 D0513 = PESD5V0S1BL: DataRecord: 2017-08-09; Geometry Height: 0.33mm; MPN: PESD5V0S1BL,315; Manufacturer: NEXPERIA; Part Description: TVS Bi Vrwm=5V 35pF SOD-882 RO; Part Number: QT0015100012; Rev.Date: 2023-07-11
J0501 = AXE530127: Application_Level: 通用; DataRecord: 2017-08-09; Geometry Height: 0.77mm; Lib_Name: 结构连接器; Manufacturer: PANASONIC; Part Description: CON B2B Socket 30pin 0.4PITCH H0.77mm RO; Part Number: QT0016301001; Rev.Date: 2022-08-17
J0502 = 50552-03001-001: Application_Level: 限制（Others）; BOMRemark: NM; DataRecord: 2023-02-22; Geometry Height: 4.35mm; Lib_Name: 结构连接器; Manufacturer: ACES; Part Description: CON BTB FEMALE 2x15Pin 1.0pitch SMT PINS32 19.5x3.4mm H4.35mm RO; Part Number: QT0016201828; Rev.Date: 2023-02-22
J0503 = 6298706220883: DataRecord: 2017-08-09; Geometry Height: 5.4mm; Manufacturer: KYOCERA; Part Description: CON  TP 6PIN 0.5mm 5.4mm RO; Part Number: QT0016601003; Rev.Date: 2022-08-17
Q0501 Q0502 = DMG2305UX-7: Application_Level: Limited(限制); BOMRemark: NM; DataRecord: 2021-11-16; Geometry Height: 1.1mm; Lib_Name: MOS管; Manufacturer: DIODES; Part Description: AUD PMOS VDS=-20V -3.6A Vth=-0.5~-0.9V 0.2mR SOT23 H1.1mm RO; Part Number: QT0015401091; Rev.Date: 2022-10-18
R0503 R0506 R0522 R0529 = R-0402: Application_Level: Common(通用); BOMRemark: NM; DataRecord: 2017-08-09; Geometry Height: 0.4MM; Lib_Name: 电阻; MPN: RC0402JR-070RL; Manufacturer: YAGEO; Part Description: RES MF 10K +/-5% 1/16W CH0402 H0.4mm RO; Part Number: QT0011000453; Rev.Date: 2021-12-15
R0504 R0510 = R-0402_v3: BOMRemark: NM; Manufacturer: YAGEO; Part Description: RES MF 10K +/-5% 1/16W CH0402 RO; Part Number: QT0011000453
R0505 R0519 = R-0402: Application_Level: 通用; BOMRemark: NM; DataRecord: 2017-08-09; Geometry Height: 0.4MM; Lib_Name: 电阻; MPN: RC0402JR-07100KL; Manufacturer: YAGEO; Part Description: RES MF 100K +/-5% 1/16W CH0402 H0.4mm RO; Part Number: QT0011000450; Rev.Date: 2022-08-17
R0508 R0517 = R-0402_v3: DataRecord: 2017-08-09; Geometry Height: 0.4MM; MPN: RC0402JR-072K2L; Manufacturer: YAGEO; Part Description: RES MF 2.2K +/-5% 1/16W CH0402 H0.4mm RO; Part Number: QT0011000522; Rev.Date: 2022-08-17
R0513 = R-0402: Application_Level: Common(通用); BOMRemark: NM; DataRecord: 2017-08-09; Geometry Height: 0.4MM; Lib_Name: 电阻; MPN: RC0402JR-0710KL; Manufacturer: YAGEO; Part Description: RES MF 0R +/-5% 1/16W CH0402 H0.4mm RO; Part Number: QT0011000094; Rev.Date: 2021-12-15
R0515 = R-0402: Application_Level: Common(通用); BOMRemark: NM; DataRecord: 2017-08-09; Geometry Height: 0.4MM; Lib_Name: 电阻; MPN: RC0402JR-0710KL; Manufacturer: YAGEO; Part Description: RES MF 10K +/-5% 1/16W CH0402 H0.4mm RO; Part Number: QT0011000453; Rev.Date: 2021-12-15
R0516 = R: BOMRemark: NM; Geometry Height: 0.5mm; Lib_Name: LIBRARY; MPN: RC0402FR-07220KL; Manufacturer: YAGEO; Part Description: RES MF 10K +/-5% 1/16W CH0402 H0.4mm RO; Part Number: QT0011000453
R0527 = R: BOMRemark: NM; Geometry Height: 0.5mm; Lib_Name: LIBRARY; MPN: RC0402FR-07220KL; Manufacturer: YAGEO; Part Description: RES MF 4.7K +/-5% 1/16W CH0402 H0.4mm RO; Part Number: QT0011000456
R0528 = R-0402_v3: BOMRemark: NM; Manufacturer: YAGEO; Part Description: RES MF 0R +/-5% 1/16W CH0402 RO; Part Number: QT0011000094
TP0501 TP0503 = TP: DataRecord: 2021-03-15; Geometry Height: 0.1mm; Lib_Name: 其他; Manufacturer: QUECTEL; Remark: Origin Imported on 2020/6/12; Rev.Date: 2021-03-15; option: @
TP0502 TP0504 = TP_1_00: option: @
U0501 U0502 = SGM2036S-2_8XN5G_TR: Application_Level: Common(通用); DataRecord: 2022-07-20; Geometry Height: 1.25mm; Lib_Name: 电源管理芯片; MPN: SGM2036S-2.8XN5G/TR; Manufacturer: SGMICRO; Part Description: PMIC LDO 1.6-5.5V 2.8V 300mA 25uA SOT23-5 2.8x2.92mm H1.25mm RO; Part Number: QT0013101651; Rev.Date: 2022-07-27
U0503 = ETA5053V180DF1E: Application_Level: 通用; BOMRemark: NM; DataRecord: 2020-01-09; Geometry Height: 0.4mm; Lib_Name: 电源管理芯片; Manufacturer: ETA; Part Description: PMIC LDO 1.6-6.0V 1.8V 300mA DFN1×1-4 H0.4mm RO; Part Number: QT0013101260; Rev.Date: 2022-08-17

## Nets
GND: C0401.1 C0402.1 C0403.2 C0404.2 C0406.2 C0407.2 C0408.2 C0409.2 C0410.1 C0412.2 C0413.1 C0501.1 C0502.1 C0504.2 C0506.1 C0507.2 C0508.2 C0511.2 C0512.1 C0514.2 C0518.2 C0519.1 C0520.1 C0521.2 C0522.1 C0523.2 C0524.1 C0525.1 C0526.1 C0527.2 C0528.2 C0530.2 C0533.2 C0535.1 D0406.2 D0407.2 D0408.2 D0410.2 D0501.2(E) D0502.5(GND1) D0502.6(GND2) D0503.2(E) D0504.1 D0505.2(E) D0506.5(GND1) D0506.6(GND2) D0507.2(E) D0509.1 D0510.1 D0511.5(GND1) D0511.6(GND2) D0512.5(GND1) D0512.6(GND2) D0513.1 D0514.5(GND1) D0514.6(GND2) J0401.2(D2_SHIELD) J0401.5(D1_SHIELD) J0401.8(D0_SHIELD) J0401.11(CLK_SHIELD) J0401.17(CEC_GND) J0401.20(GND1) J0401.21(GND2) J0401.22(GND3) J0401.23(GND4) J0402.4 J0402.7 J0402.8 J0403.7 J0403.10 J0403.13 J0403.16 J0403.19 J0403.22 J0403.25 J0403.30 J0403.41 J0403.42 J0501.12(GND1) J0501.16(GND2) J0501.19(GND3) J0501.22(GND4) J0501.25(GND5) J0501.28(GND6) J0501.31 J0501.32 J0501.33 J0501.34 J0502.5 J0502.12 J0502.15 J0502.18 J0502.21 J0502.24 J0502.27 J0502.31 J0502.32 J0503.5(GND) J0503.7 J0503.8 Q0402.2(E) Q0403.2(E) Q0404.2(E) R0413.1 R0422.1 R0425.2 R0507.1 R0512.1 R0516.1 R0518.1 R0519.1 R0530.1 U0403.5(GND1) U0403.6(GND2) U0404.5(GND1) U0404.6(GND2) U0408.5(GND1) U0408.6(GND2) U0409.3(GND1) U0409.7(GND2) U0411.5(GND1) U0411.6(GND2) U0501.2(GND) U0502.2(GND) U0503.2(GND2) U0503.5(GND1) U0504.3(GND1) U0504.7(GND2) ; also on sheet 1 2 3 6 7 8 9 10 11 12 13 14
VBATT: C0501.2 C0502.2 C0512.2 C0530.1 L0501.1 R0504.2 R0510.2 R0515.2 U0501.1(IN) U0502.1(IN) U0503.4(VIN) U0504.6(VIN) ; also on sheet 1 2 11
VCC_PMUIO2: R0508.2 R0517.2 ; also on sheet 11 12
VCCA1V8_IMAGE: R0511.1 ; also on sheet 12 13
VCCIO4: U0407.1(G) U0410.1(G) ; also on sheet 11 12
VCCIO7: D0404.1(G) R0405.2 R0417.2 R0428.2 U0405.1(G) U0413.1(G) ; also on sheet 12
VCCIO_ACODEC: Q0405.1(G) R0403.2 ; also on sheet 9 12
VDD_2V8: B0503.2 C0507.1 C0508.1 J0501.14(VIO28) TP0504.1
4G_PWREN_H_GPIO0_C6: D0501.1(B) ; also on sheet 12
100OHM_EDP_TX_AUXN: C0515.2 ; also on sheet 13
100OHM_EDP_TX_AUXN1: C0515.1 J0502.13 R0505.2
100OHM_EDP_TX_AUXP: C0536.1 ; also on sheet 13
100OHM_EDP_TX_AUXP1: C0536.2 J0502.14 R0519.2
100OHM_EDP_TX_D0N: C0509.2 ; also on sheet 13
100OHM_EDP_TX_D0N1: C0509.1 J0502.17
100OHM_EDP_TX_D0P: C0534.1 ; also on sheet 13
100OHM_EDP_TX_D0P1: C0534.2 J0502.16
100OHM_EDP_TX_D1N: C0531.2 ; also on sheet 13
100OHM_EDP_TX_D1N1: C0531.1 J0502.20
100OHM_EDP_TX_D1P: C0513.1 ; also on sheet 13
100OHM_EDP_TX_D1P1: C0513.2 J0502.19
100OHM_EDP_TX_D2N: C0529.2 ; also on sheet 13
100OHM_EDP_TX_D2N1: C0529.1 J0502.23
100OHM_EDP_TX_D2P: C0505.1 ; also on sheet 13
100OHM_EDP_TX_D2P1: C0505.2 J0502.22
100OHM_EDP_TX_D3N: C0510.2 ; also on sheet 13
100OHM_EDP_TX_D3N1: C0510.1 J0502.26
100OHM_EDP_TX_D3P: C0532.1 ; also on sheet 13
100OHM_EDP_TX_D3P1: C0532.2 J0502.25
100OHM_HDMI_CLK_N_1: J0401.12(CLK-) R0462.2 U0408.4
100OHM_HDMI_CLK_P_1: J0401.10(CLK+) R0461.2 U0408.3
100OHM_HDMI_TX0_N_1: J0401.9(D0-) R0460.2 U0404.4
100OHM_HDMI_TX0_P_1: J0401.7(D0+) R0459.2 U0404.3
100OHM_HDMI_TX0N_PORT: R0460.1 U0404.2 ; also on sheet 13
100OHM_HDMI_TX0P_PORT: R0459.1 U0404.1 ; also on sheet 13
100OHM_HDMI_TX1_N_1: J0401.6(D1-) R0458.2 U0411.4
100OHM_HDMI_TX1_P_1: J0401.4(D1+) R0457.2 U0411.3
100OHM_HDMI_TX1N_PORT: R0458.1 U0411.2 ; also on sheet 13
100OHM_HDMI_TX1P_PORT: R0457.1 U0411.1 ; also on sheet 13
100OHM_HDMI_TX2_N_1: J0401.3(D2-) R0466.2 U0403.4
100OHM_HDMI_TX2_P_1: J0401.1(D2+) R0455.2 U0403.3
100OHM_HDMI_TX2N_PORT: R0466.1 U0403.2 ; also on sheet 13
100OHM_HDMI_TX2P_PORT: R0455.1 U0403.1 ; also on sheet 13
100OHM_HDMI_TXCLKN_PORT: R0462.1 U0408.2 ; also on sheet 13
100OHM_HDMI_TXCLKP_PORT: R0461.1 U0408.1 ; also on sheet 13
100OHM_MIPI_DSI_TX0_CLKN: J0403.17 ; also on sheet 13
100OHM_MIPI_DSI_TX0_CLKP: J0403.18 ; also on sheet 13
100OHM_MIPI_DSI_TX0_D0N: J0403.8 ; also on sheet 13
100OHM_MIPI_DSI_TX0_D0P: J0403.9 ; also on sheet 13
100OHM_MIPI_DSI_TX0_D1N: J0403.11 ; also on sheet 13
100OHM_MIPI_DSI_TX0_D1P: J0403.12 ; also on sheet 13
100OHM_MIPI_DSI_TX0_D2N: J0403.14 ; also on sheet 13
100OHM_MIPI_DSI_TX0_D2P: J0403.15 ; also on sheet 13
100OHM_MIPI_DSI_TX0_D3N: J0403.20 ; also on sheet 13
100OHM_MIPI_DSI_TX0_D3P: J0403.21 ; also on sheet 13
100OHM_MIPI_DSI_TX1_CLKN: D0506.2 R0575.1 ; also on sheet 13
100OHM_MIPI_DSI_TX1_CLKN_1: D0506.4 J0501.30(MIPI_TCN) R0575.2
100OHM_MIPI_DSI_TX1_CLKP: D0506.1 R0574.1 ; also on sheet 13
100OHM_MIPI_DSI_TX1_CLKP_1: D0506.3 J0501.29(MIPI_TCP) R0574.2
100OHM_MIPI_DSI_TX1_D0N: D0502.2 R0573.1 ; also on sheet 13
100OHM_MIPI_DSI_TX1_D0N_1: D0502.4 J0501.27(MIPI_TDN0) R0573.2
100OHM_MIPI_DSI_TX1_D0P: D0502.1 R0572.1 ; also on sheet 13
100OHM_MIPI_DSI_TX1_D0P_1: D0502.3 J0501.26(MIPI_TDP0) R0572.2
100OHM_MIPI_DSI_TX1_D1N: D0512.2 R0571.1 ; also on sheet 13
100OHM_MIPI_DSI_TX1_D1N_1: D0512.4 J0501.24(MIPI_TDN1) R0571.2
100OHM_MIPI_DSI_TX1_D1P: D0512.1 R0570.1 ; also on sheet 13
100OHM_MIPI_DSI_TX1_D1P_1: D0512.3 J0501.23(MIPI_TDP1) R0570.2
100OHM_MIPI_DSI_TX1_D2N: D0511.2 R0569.1 ; also on sheet 13
100OHM_MIPI_DSI_TX1_D2N_1: D0511.4 J0501.21(MIPI_TDN2) R0569.2
100OHM_MIPI_DSI_TX1_D2P: D0511.1 R0568.1 ; also on sheet 13
100OHM_MIPI_DSI_TX1_D2P_1: D0511.3 J0501.20(MIPI_TDP2) R0568.2
100OHM_MIPI_DSI_TX1_D3N: D0514.2 R0567.1 ; also on sheet 13
100OHM_MIPI_DSI_TX1_D3N_1: D0514.4 J0501.18(MIPI_TDN3) R0567.2
100OHM_MIPI_DSI_TX1_D3P: D0514.1 R0566.1 ; also on sheet 13
100OHM_MIPI_DSI_TX1_D3P_1: D0514.3 J0501.17(MIPI_TDP3) R0566.2
CEC_HDMI: D0404.3(D) D0408.1 J0401.13(CEC) R0416.1
DC12V: C0516.2 C0520.2 Q0502.2(S) R0503.1 R0509.1 ; also on sheet 1 6 9 14
EDP_BL_EN: D0505.3(C) J0502.10 R0522.1
EDP_DET: R0516.2 R0527.2 ; also on sheet 12
eDP_HPD: J0502.11 R0527.1
eDP_PWM: D0501.3(C) J0502.8 R0506.1
EDP_VDDIN: C0518.1 C0523.1 J0502.1 J0502.2 J0502.3 Q0501.3(D) R0506.2 R0522.2 R0525.2
eDP_VLED: C0506.2 C0522.2 J0502.28 Q0502.3(D) R0509.2
EXT_EN: R0526.2 ; also on sheet 1 6 13
FSPI_D0/FLASH_RDY: D0505.1(B) ; also on sheet 12
GPIO3_D1: D0503.1(B) D0507.1(B) ; also on sheet 12
HDMI14_TX_PWREN_H_GPIO0_D5: Q0402.1(B) ; also on sheet 12
HDMI_5V: C0413.2 D0403.1 J0401.18(VCC5V) R0408.2
HDMI_TX_HPD_PORT: D0410.1 J0401.19(DETECT) R0401.1 R0425.1
HDMI_TX_HPDIN: R0401.2 ; also on sheet 13
HDMITX_CEC_M0: D0404.2(S) R0428.1 ; also on sheet 12
HDMITX_SCL: R0405.1 U0413.2(S) ; also on sheet 12
HDMITX_SCL_M: D0407.1 J0401.15(SCL) R0426.1 U0413.3(D)
HDMITX_SDA: R0417.1 U0405.2(S) ; also on sheet 12
HDMITX_SDA_M: D0406.1 J0401.16(SDA) R0420.1 U0405.3(D)
I2C1_SCL_TP: D0504.2 J0503.2(SCL) R0517.1 ; also on sheet 11 12
I2C1_SDA_TP: D0509.2 J0503.1(SDA) R0508.1 ; also on sheet 11 12
I2C4_SCL_M1: R0430.2 U0410.2(S) ; also on sheet 11 12
I2C4_SDA_M1: R0424.2 U0407.2(S) ; also on sheet 11 12
LCD0_BL_PWM4: R0422.2 U0409.5(CTRL) ; also on sheet 12
LCD1_BL_PWM5: R0512.2 U0504.5(CTRL) ; also on sheet 12
LCD_RST_L_GPIO3_C7: J0501.6(RESET) ; also on sheet 12
LCDC_D1: R0504.1 R0507.2 U0502.3(EN) ; also on sheet 12
LCDC_D21: Q0403.1(B) R0406.2 ; also on sheet 12
LCM_LED+: J0501.1(LEDA) R0523.1
LCM_LED-: J0501.3(LEDK) R0530.2 U0504.1(FB)
LCMIO_1V8: C0519.2 J0501.13(VIO18) R0511.2 R0513.1
LVDS_CTP28: B0501.2 C0403.1 J0402.5 R0404.2 R0414.2 R0415.2 R0429.2
LVDS_LEDA: J0403.39 J0403.40 R0402.1
LVDS_LEDK: J0403.31 J0403.32 R0413.2 U0409.1(FB)
LVDS_RESET: C0404.1 J0403.5 Q0403.3(C) R0406.1 R0421.1
LVDS_TP_INT: J0402.3 Q0405.3(D) R0404.1 R0409.1
LVDS_TP_RST: C0406.1 J0402.6 Q0404.3(C) R0418.1 R0429.1
LVDS_TP_SCL: J0402.1 R0414.1 R0430.1 U0410.3(D)
LVDS_TP_SDA: J0402.2 R0415.1 R0424.1 U0407.3(D)
LVDS_VDD3V3: C0407.1 J0403.2 J0403.3 Q0401.3(D) R0421.2 R0427.1
MIPI_CTP28: B0502.2 C0533.1 J0503.6(VDD)
PDM_SDI1_M0_ADC: Q0405.2(S) R0403.1 R0409.2 ; also on sheet 11 12
PDM_SDI2_M0_ADC: Q0404.1(B) R0418.2 ; also on sheet 11 12
SARADC_VIN7: R0528.2 ; also on sheet 11 13
TP_INT_L_GPIO0_B5: D0510.2 J0503.4(INT) ; also on sheet 12
TP_RST_L_GPIO0_B6: D0513.2 J0503.3(RESET) ; also on sheet 12
VDC_3V3: C0402.2 C0405.2 C0409.1 C0517.2 C0521.1 D0401.2 L0401.1 Q0401.2(S) Q0501.2(S) R0407.1 R0427.2 R0505.1 R0525.1 R0529.1 U0409.6(VIN) ; also on sheet 1 8 10 11
VDC_5V: C0401.2 C0410.2 D0402.2 D0403.2 R0408.1 ; also on sheet 1
N16851360: B0501.1 B0502.1 C0526.2 U0501.5(OUT)
N16851388: R0510.1 R0518.2 R0526.1 U0501.3(EN)
N16851406: C0511.1 U0501.4(BP/FB)
N16851801: C0504.1 C0527.1 D0508.1 R0523.2
N16851821: D0508.2 L0501.2 U0504.4(SW)
N17248848: B0503.1 C0524.2 C0528.1 U0502.5(OUT)
N17248866: C0514.1 U0502.4(BP/FB)
N17269506: C0525.2 R0515.1 U0503.3(EN)
N17270599: C0535.2 R0513.2 U0503.1(VOUT)
N17274420: J0501.7(LCD_ID) R0528.1
N17654307: J0501.5(LPTE) TP0502.1
N18247329: D0402.1 R0420.2 R0426.2
N18365015: C0408.1 C0412.1 D0405.1 R0402.2
N18365073: D0405.2 L0401.2 U0409.4(SW)
N18366438: C0405.1 Q0401.1(G) Q0402.3(C) R0407.2
N18378711: C0517.1 D0507.3(C) Q0501.1(G) R0529.2
N18380308: C0516.1 D0503.3(C) Q0502.1(G) R0503.2
N18382144: J0502.9 TP0503.1
N18382149: J0502.30 TP0501.1
N18618933: D0401.1 R0416.2

Not connected (* = marked no-connect by the designer): J0401 14(NC)*; J0403 1* 4* 6* 23* 24* 26* 27* 28* 29* 33* 34* 35* 36* 37* 38*; J0501 2(NC1)* 4(NC2)* 8(NC(SDA-TP))* 9(NC(SCL-TP))* 10(NC(RST-TP))* 11(NC(EINT-TP))* 15(NC(VTP-TP))*; J0502 4* 6* 7* 29*; U0409 2(NC)*; U0504 2(NC)*

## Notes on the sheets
sheet 4
- LVDS LCM连接器
- HDMI OUT
- NC
- VDD_3V3
- VDD_3V3
- NC
- RESET
- NC
- GND
- RXIN0-
- RXIN0+
- GND
- RXIN1-
- RXIN1+
- GND
- RXIN2-
- RXIN2+
- GND
- RXCLKIN-
- RXCLKIN+
- GND
- RXIN3-
- RXIN3+
- GND
- NC
- NC
- GND
- NC
- NC
- NC
- NC
- GND
- LEDK
- LEDK
- NC
- NC
- NC
- NC
- NC
- NC
- LEDA
- LEDA
- LVDS TP连接器
- LVDS 3.3供电
- TP_SCL
- TP_SDA
- TP_INT
- GND
- TP_VCC
- TP_RST
- 0.5A
- 0.5A
- HDMI 5V POWER
- 0.5A
- LVDS 背光
- RK推荐1.8K
sheet 5
- MIPI LCM
- eDP连接器
- VDDIN
- VDDIN
- MIPI TP
- VDDIN
- NC
- GND
- NC
- NC
- PWM
- CABC
- BL_EN
- HPD
- GND
- DAUXN
- DAUXP
- GND
- DRX0P
- DRX0N
- GND
- DRX1P
- DRX1N
- GND
- DRX2P
- DRX2N
- GND
- DRX3P
- DRX3N
- GND
- VLED
- NC
- BIST
- 200mA
- eDP 3.3供电
- 200mA
- 0.6A
- 0.6A
- eDP 12V背光
- 0.8A
- 0.8A
- 考虑阻值是否调低
- 300mA
- 300mA
